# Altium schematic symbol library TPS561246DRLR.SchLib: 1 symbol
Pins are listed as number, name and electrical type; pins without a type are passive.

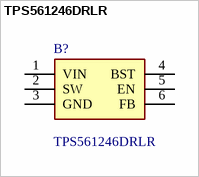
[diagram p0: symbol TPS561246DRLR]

## TPS561246DRLR
designator B?
Switching Voltage Regulators 4.2V to 17V input voltage, 1A, 1.2MHz synchronous buck converter in SOT563 with FCCM mode; Manufacturer_Name: Texas Instruments; Geometry.Height: 0.6mm
footprint SOTFL50P160X60-6N
pins: 1 VIN, 2 SW, 3 GND, 4 BST, 5 EN, 6 FB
